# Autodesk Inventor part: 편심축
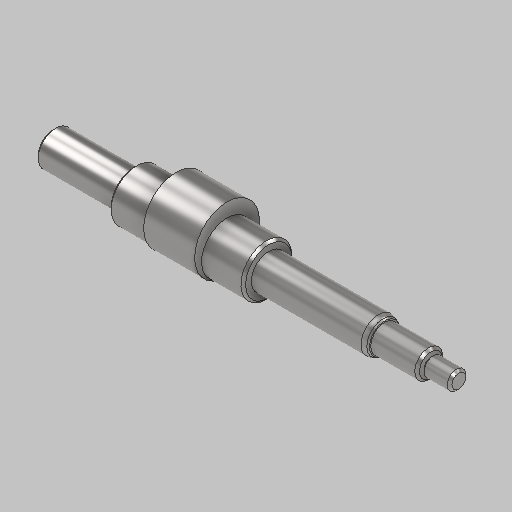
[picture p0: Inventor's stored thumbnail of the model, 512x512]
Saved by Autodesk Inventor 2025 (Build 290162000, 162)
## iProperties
Created: 2024-07
Part Number: 편심축
Material: 강철, 연강
Document SubType Name: Modeling
Designer: 현기
Density: 7.86 g/cm^3
Appearance: 기본값
Author: jhkim
Sending System: Autodesk Inventor 2025
Preprocessor: ST-DEVELOPER v20
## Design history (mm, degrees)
feature "솔리드1"
node "솔리드2"
